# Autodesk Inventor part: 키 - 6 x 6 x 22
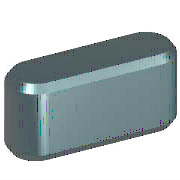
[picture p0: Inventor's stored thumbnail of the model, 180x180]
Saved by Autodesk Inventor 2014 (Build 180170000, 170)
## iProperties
IsCustomPart: 1
Created: 2012-02
Part Number: 키 - 6 x 6 x 22
Material: 강철, 연강
Description: 키 및 해당 키홈
Document SubType Name: Modeling
Standard: KS B 1311
Designer: mduedu
Standards Organization: KS
Language: ko-KR
Size Designation: 6 x 6 x 22
Categories: <MemberInstance><Categories><Category DisplayName="샤프트 부품" InternalName="7f7aeb1f-a693-4053-b835-cee3144e0d98" Mnemonic="SHFT"><Category DisplayName="키" Interna
Density: 7.86 g/cm^3
Mass: 5.79788 g
Surface Area: 5.294 cm^2
Volume: 0.737644 cm^3
Appearance: Steel
Author: mduedu
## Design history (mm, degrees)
sketch "스케치1"
  geometry: L1 (3, 3)-(19, 3); L2 (19, -3)-(3, -3); L3 (0, 9.4)-(0, -7.4) reference; L4 (-5, 0)-(30, 0) reference; L5 (22, 0)-(22, 7); A1 r 3 centre (3, 0) between (3, 3) and (3, -3); A2 r 3 centre (19, 0) between (19, -3) and (19, 3)
  constraints: 6 end point, 5 point on circle, 4 tangent, 3 point on line, 2 centre point, 1 horizontal, 1 parallel, 1 perpendicular
  dimensions: "d0" = 3 radius of A1 (= 0.5 x PB); "d13" = 3 radius of A2 (= 0.5 x PB); "d14" = 22 distance between parallel lines of L5 L3 (= NLG)
extrude "본체1" new body sketch "스케치1" taper "d3" = 0 deg; stored distance "d4" = 10
workplane "Work Plane3"
body "Solid1"
workplane "Work Plane1"
workplane "Work Plane2"
chamfer "모따기1" distance "d8" = 0.4 (= PHH); stored, may be unused: second distance "d9" = 0.4 (= PHH), angle "d15" = 45 deg
other parameters: "d1" = -3.5 (= -PNT), "d2" = 2.5 (= PH - PNT), "NLG" = 22 [user parameter; used in 3 equation terms], "PB" = 6 [user parameter; used in 2 equation terms], "PNT" = 3.5 [user parameter; used in 2 equation terms], "PH" = 6 [user parameter; used in 1 equation term], "PHH" = 0.4 [user parameter; used in 2 equation terms], "d10" = 0, "d16" = 0, "d17" = 0, "d18" = 0, "WDMIN" = 17 [user parameter], "PLB2" = 22 (= NLG) [user parameter], "WDMAX" = 22 [user parameter], "PLB1" = 22 (= NLG) [user parameter], "RR" = 0.16 [user parameter], "PUEB" = 2.8 [user parameter]
